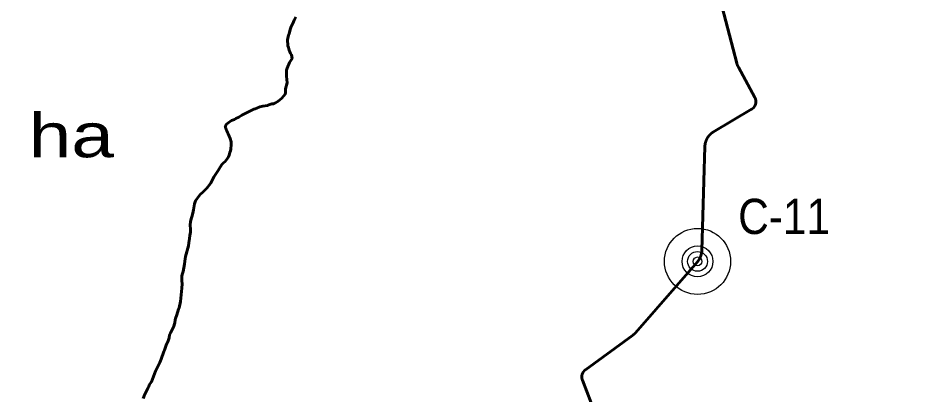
# Model space of a CAD drawing. Extents: x -1643653 to 4543381, y 1624270 to 13878484.
# Drawn here: x 645322 to 655603, y 8957191 to 8961468 of the extents above; entities that cross this region are included whole.
import ezdxf

# ---------------------------------------------------------------- set-up
doc = ezdxf.new("R2010")
doc.units = 0
doc.header["$LTSCALE"] = 200
for name, color, linetype, lineweight in [('1', 7, 'Continuous', 13), ('15', 7, 'Continuous', 25), ('24', 7, 'Continuous', 25), ('27', 7, 'Continuous', 53), ('60', 7, 'Continuous', 53)]:
    doc.layers.add(name, color=color, linetype=linetype, lineweight=lineweight)
doc.layers.add('63', color=7, linetype='Continuous')

msp = doc.modelspace()

# ---------------------------------------------------------------- linework, layer by layer
at = {"layer": '1', "lineweight": 25}
msp.add_spline([(814781, 9009175.5), (814787.2, 9009173.4), (814796.9, 9009173.4), (814799.4, 9009172.4), (814805.1, 9009174.5), (814805.6, 9009176.5), (814811.7, 9009179.5), (814811.7, 9009179.5), (814801.5, 9009181), (814790.7, 9009181.5), (814784.1, 9009183.1), (814777.4, 9009185.1), (814778.4, 9009175.5)], degree=3, dxfattribs=at)
at = {"layer": '15'}
for radius in [375, 175, 112.5, 50]:
    msp.add_circle((653034.2, 8958706.4), radius, dxfattribs=at)
at = {"layer": '24', "lineweight": 53}
for points in [[(648474.8, 8961478.5), (648456.4, 8961445.7), (648449.2, 8961427.1), (648419.2, 8961360.9), (648410.6, 8961337.9), (648398, 8961290.7), (648391.5, 8961272.8), (648380.9, 8961222.2), (648380.9, 8961222.2), (648379.8, 8961206.8), (648384.7, 8961171.6), (648385.1, 8961152.9)], [(648385.1, 8961152.9), (648390, 8961133.3), (648400.4, 8961103), (648415.7, 8961067.9), (648425.4, 8961050), (648432.1, 8961011), (648401.9, 8960963.6), (648376.2, 8960898.2), (648370.1, 8960878.6), (648367.8, 8960859.9), (648367.9, 8960810.1), (648376.5, 8960734.5), (648357.4, 8960665.8), (648358.8, 8960619.8), (648351.9, 8960604.5), (648338.8, 8960585.2), (648311.2, 8960556.4), (648291.8, 8960541.2), (648269.8, 8960521), (648236.7, 8960501.1), (648220, 8960496.4), (648202.2, 8960494.8), (648170.1, 8960481.9), (648153, 8960477.4), (648100.1, 8960468.4), (648066.6, 8960460), (648032.2, 8960447.3), (648014.3, 8960438.5), (647997.2, 8960433), (647928.7, 8960400.9), (647863.5, 8960365.3), (647826.2, 8960342.8), (647793.8, 8960329), (647778, 8960318.3), (647744.3, 8960305.3), (647701.1, 8960277.2), (647689.4, 8960265.4), (647679.9, 8960250.9), (647675, 8960238.2), (647674.2, 8960228.6), (647680.1, 8960220.4), (647683.5, 8960203.8), (647689.9, 8960186.8), (647698.1, 8960170.3), (647708.3, 8960153.8), (647730.9, 8960100.4), (647739.1, 8960063.9), (647740.2, 8960032), (647736.1, 8959980.6), (647731.8, 8959962.6), (647725, 8959943.9), (647716.7, 8959911.2), (647708.7, 8959892.6), (647696.4, 8959871.2), (647672.6, 8959842), (647653.3, 8959825.7), (647636.4, 8959806.1), (647604.7, 8959757.9), (647594, 8959736.3), (647570, 8959703.3), (647547.8, 8959670.1), (647506.1, 8959591.7), (647464.3, 8959538.3), (647419.4, 8959492.2), (647388.5, 8959466.3), (647353, 8959421.6), (647336.2, 8959394.4), (647325.8, 8959358.5), (647311.8, 8959293.5), (647311.1, 8959273.8), (647298.8, 8959224.9), (647287.2, 8959190.6), (647279.5, 8959155.6), (647275.4, 8959122.1), (647277.5, 8959069.1), (647277.3, 8959036.4), (647271.1, 8959002.1), (647267.7, 8958967.1), (647258.4, 8958917.2), (647255, 8958883), (647222.6, 8958760.6), (647213.1, 8958710), (647209.8, 8958675.8), (647197.2, 8958591.6), (647186.1, 8958559), (647181, 8958538.7), (647179, 8958522.3), (647180.3, 8958485.5), (647185.2, 8958453), (647182.2, 8958403.1), (647164.1, 8958249.7), (647150.1, 8958180.3), (647142.6, 8958162.4), (647125.2, 8958100), (647110, 8958058), (647106, 8958041.7), (647101.7, 8958008.2), (647087.2, 8957958.4), (647087.2, 8957958.4), (647058.3, 8957911.3), (647050.3, 8957890.4)], [(647050.3, 8957890.4), (647042.3, 8957873.9), (647037.4, 8957839), (647027, 8957805.4), (647004.7, 8957754), (646983.9, 8957699.7), (646975.5, 8957682.5), (646947.2, 8957596.2), (646930.5, 8957560.2), (646917.2, 8957527.6), (646883.4, 8957459.8), (646834.7, 8957341.3), (646821.9, 8957322.3), (646811.7, 8957303.4), (646805, 8957286.3), (646794.6, 8957269.1), (646788.3, 8957250.5), (646761.3, 8957200.6), (646741.4, 8957150.7)]]:
    msp.add_lwpolyline(points, dxfattribs=at)
at = {"layer": '27'}
for points in [[(653189, 8962072.5), (653480.5, 8960954.9), (653480.7, 8960954.4), (653481.7, 8960950.6), (653482.8, 8960946.7), (653484.1, 8960942.9), (653485.3, 8960939.1), (653486.7, 8960935.4), (653488.2, 8960931.6), (653489.7, 8960927.9), (653491.2, 8960924.2), (653492.9, 8960920.6), (653494.6, 8960917), (653496.4, 8960913.4), (653498.3, 8960909.9), (653684.6, 8960567.2), (653684.8, 8960566.8), (653686.1, 8960564.3), (653687.3, 8960561.7), (653688.5, 8960559.2), (653689.6, 8960556.5), (653690.6, 8960553.9), (653691.5, 8960551.2), (653692.4, 8960548.5), (653693.2, 8960545.8), (653693.9, 8960543.1), (653694.5, 8960540.3), (653695.1, 8960537.6), (653695.5, 8960534.8), (653695.9, 8960532), (653696.2, 8960529.2), (653696.5, 8960526.3), (653696.6, 8960523.5)], [(653189, 8962072.5), (653480.5, 8960954.9), (653480.7, 8960954.4), (653481.7, 8960950.6), (653482.8, 8960946.7), (653484.1, 8960942.9), (653485.3, 8960939.1), (653486.7, 8960935.4), (653488.2, 8960931.6), (653489.7, 8960927.9), (653491.2, 8960924.2), (653492.9, 8960920.6), (653494.6, 8960917), (653496.4, 8960913.4), (653498.3, 8960909.9), (653684.6, 8960567.2), (653684.8, 8960566.8), (653686.1, 8960564.3), (653687.3, 8960561.7), (653688.5, 8960559.2), (653689.6, 8960556.5), (653690.6, 8960553.9), (653691.5, 8960551.2), (653692.4, 8960548.5), (653693.2, 8960545.8), (653693.9, 8960543.1), (653694.5, 8960540.3), (653695.1, 8960537.6), (653695.5, 8960534.8), (653695.9, 8960532), (653696.2, 8960529.2), (653696.5, 8960526.3), (653696.6, 8960523.5)], [(648385.1, 8961152.9), (648384.7, 8961171.6), (648379.8, 8961206.8), (648380.9, 8961222.2), (648380.9, 8961222.2), (648391.5, 8961272.8), (648398, 8961290.7), (648410.6, 8961337.9), (648419.2, 8961360.9), (648449.2, 8961427.1), (648456.4, 8961445.7), (648474.8, 8961478.5)], [(648385.1, 8961152.9), (648384.7, 8961171.6), (648379.8, 8961206.8), (648380.9, 8961222.2), (648380.9, 8961222.2), (648391.5, 8961272.8), (648398, 8961290.7), (648410.6, 8961337.9), (648419.2, 8961360.9), (648449.2, 8961427.1), (648456.4, 8961445.7), (648474.8, 8961478.5)], [(647050.3, 8957890.4), (647058.3, 8957911.3), (647087.2, 8957958.4), (647087.2, 8957958.4), (647101.7, 8958008.2), (647106, 8958041.7), (647110, 8958058), (647125.2, 8958100), (647142.6, 8958162.4), (647150.1, 8958180.3), (647164.1, 8958249.7), (647182.2, 8958403.1), (647185.2, 8958453), (647180.3, 8958485.5), (647179, 8958522.3), (647181, 8958538.7), (647186.1, 8958559), (647197.2, 8958591.6), (647209.8, 8958675.8), (647213.1, 8958710), (647222.6, 8958760.6), (647255, 8958883), (647258.4, 8958917.2), (647267.7, 8958967.1), (647271.1, 8959002.1), (647277.3, 8959036.4), (647277.5, 8959069.1), (647275.4, 8959122.1), (647279.5, 8959155.6), (647287.2, 8959190.6), (647298.8, 8959224.9), (647311.1, 8959273.8), (647311.8, 8959293.5), (647325.8, 8959358.5), (647336.2, 8959394.4), (647353, 8959421.6), (647388.5, 8959466.3), (647419.4, 8959492.2), (647464.3, 8959538.3), (647506.1, 8959591.7), (647547.8, 8959670.1), (647570, 8959703.3), (647594, 8959736.3), (647604.7, 8959757.9), (647636.4, 8959806.1), (647653.3, 8959825.7), (647672.6, 8959842), (647696.4, 8959871.2), (647708.7, 8959892.6), (647716.7, 8959911.2), (647725, 8959943.9), (647731.8, 8959962.6), (647736.1, 8959980.6), (647740.2, 8960032), (647739.1, 8960063.9), (647730.9, 8960100.4), (647708.3, 8960153.8), (647698.1, 8960170.3), (647689.9, 8960186.8), (647683.5, 8960203.8), (647680.1, 8960220.4), (647674.2, 8960228.6), (647675, 8960238.2), (647679.9, 8960250.9), (647689.4, 8960265.4), (647701.1, 8960277.2), (647744.3, 8960305.3), (647778, 8960318.3), (647793.8, 8960329), (647826.2, 8960342.8), (647863.5, 8960365.3), (647928.7, 8960400.9), (647997.2, 8960433), (648014.3, 8960438.5), (648032.2, 8960447.3), (648066.6, 8960460), (648100.1, 8960468.4), (648153, 8960477.4), (648170.1, 8960481.9), (648202.2, 8960494.8), (648220, 8960496.4), (648236.7, 8960501.1), (648269.8, 8960521), (648291.8, 8960541.2), (648311.2, 8960556.4), (648338.8, 8960585.2), (648351.9, 8960604.5), (648358.8, 8960619.8), (648357.4, 8960665.8), (648376.5, 8960734.5), (648367.9, 8960810.1), (648367.8, 8960859.9), (648370.1, 8960878.6), (648376.2, 8960898.2), (648401.9, 8960963.6), (648432.1, 8961011), (648425.4, 8961050), (648415.7, 8961067.9), (648400.4, 8961103), (648390, 8961133.3), (648385.1, 8961152.9)], [(647050.3, 8957890.4), (647058.3, 8957911.3), (647087.2, 8957958.4), (647087.2, 8957958.4), (647101.7, 8958008.2), (647106, 8958041.7), (647110, 8958058), (647125.2, 8958100), (647142.6, 8958162.4), (647150.1, 8958180.3), (647164.1, 8958249.7), (647182.2, 8958403.1), (647185.2, 8958453), (647180.3, 8958485.5), (647179, 8958522.3), (647181, 8958538.7), (647186.1, 8958559), (647197.2, 8958591.6), (647209.8, 8958675.8), (647213.1, 8958710), (647222.6, 8958760.6), (647255, 8958883), (647258.4, 8958917.2), (647267.7, 8958967.1), (647271.1, 8959002.1), (647277.3, 8959036.4), (647277.5, 8959069.1), (647275.4, 8959122.1), (647279.5, 8959155.6), (647287.2, 8959190.6), (647298.8, 8959224.9), (647311.1, 8959273.8), (647311.8, 8959293.5), (647325.8, 8959358.5), (647336.2, 8959394.4), (647353, 8959421.6), (647388.5, 8959466.3), (647419.4, 8959492.2), (647464.3, 8959538.3), (647506.1, 8959591.7), (647547.8, 8959670.1), (647570, 8959703.3), (647594, 8959736.3), (647604.7, 8959757.9), (647636.4, 8959806.1), (647653.3, 8959825.7), (647672.6, 8959842), (647696.4, 8959871.2), (647708.7, 8959892.6), (647716.7, 8959911.2), (647725, 8959943.9), (647731.8, 8959962.6), (647736.1, 8959980.6), (647740.2, 8960032), (647739.1, 8960063.9), (647730.9, 8960100.4), (647708.3, 8960153.8), (647698.1, 8960170.3), (647689.9, 8960186.8), (647683.5, 8960203.8), (647680.1, 8960220.4), (647674.2, 8960228.6), (647675, 8960238.2), (647679.9, 8960250.9), (647689.4, 8960265.4), (647701.1, 8960277.2), (647744.3, 8960305.3), (647778, 8960318.3), (647793.8, 8960329), (647826.2, 8960342.8), (647863.5, 8960365.3), (647928.7, 8960400.9), (647997.2, 8960433), (648014.3, 8960438.5), (648032.2, 8960447.3), (648066.6, 8960460), (648100.1, 8960468.4), (648153, 8960477.4), (648170.1, 8960481.9), (648202.2, 8960494.8), (648220, 8960496.4), (648236.7, 8960501.1), (648269.8, 8960521), (648291.8, 8960541.2), (648311.2, 8960556.4), (648338.8, 8960585.2), (648351.9, 8960604.5), (648358.8, 8960619.8), (648357.4, 8960665.8), (648376.5, 8960734.5), (648367.9, 8960810.1), (648367.8, 8960859.9), (648370.1, 8960878.6), (648376.2, 8960898.2), (648401.9, 8960963.6), (648432.1, 8961011), (648425.4, 8961050), (648415.7, 8961067.9), (648400.4, 8961103), (648390, 8961133.3), (648385.1, 8961152.9)], [(653696.6, 8960523.5), (653696.7, 8960520.7), (653696.7, 8960517.8), (653696.6, 8960515), (653696.5, 8960512.2), (653696.2, 8960509.4), (653695.9, 8960506.6), (653695.5, 8960503.8), (653695, 8960501), (653694.4, 8960498.2), (653693.8, 8960495.5), (653693.1, 8960492.7), (653692.3, 8960490), (653691.4, 8960487.3), (653690.5, 8960484.7), (653689.4, 8960482), (653688.3, 8960479.4), (653687.2, 8960476.8), (653685.9, 8960474.3), (653684.6, 8960471.8), (653683.2, 8960469.3), (653681.8, 8960466.9), (653680.3, 8960464.5), (653678.7, 8960462.2), (653677, 8960459.9), (653675.3, 8960457.6), (653673.5, 8960455.4), (653671.7, 8960453.3), (653669.8, 8960451.2), (653667.8, 8960449.2), (653665.8, 8960447.2), (653663.7, 8960445.2), (653661.6, 8960443.4), (653659.4, 8960441.6), (653657.2, 8960439.8), (653654.9, 8960438.1), (653652.6, 8960436.5), (653650.2, 8960435), (653647.8, 8960433.5), (653215.1, 8960176.1), (653214.3, 8960175.7), (653210.9, 8960173.6), (653207.5, 8960171.4), (653204.2, 8960169.2), (653200.9, 8960166.9), (653197.7, 8960164.5), (653194.5, 8960162.1), (653191.4, 8960159.6), (653188.3, 8960157), (653185.3, 8960154.4), (653182.3, 8960151.8), (653179.4, 8960149), (653176.5, 8960146.2), (653173.7, 8960143.4), (653171, 8960140.5), (653168.3, 8960137.5), (653165.6, 8960134.5), (653163.1, 8960131.5), (653160.5, 8960128.3), (653158.1, 8960125.2), (653155.7, 8960122), (653153.4, 8960118.7), (653151.1, 8960115.4), (653148.9, 8960112.1), (653146.8, 8960108.7), (653144.8, 8960105.3), (653142.8, 8960101.8), (653140.8, 8960098.3), (653139, 8960094.7), (653137.2, 8960091.1), (653135.5, 8960087.5), (653133.9, 8960083.9), (653132.3, 8960080.2), (653130.9, 8960076.5), (653129.5, 8960072.7), (653128.1, 8960069), (653126.9, 8960065.2), (653125.7, 8960061.3), (653124.6, 8960057.5), (653123.6, 8960053.6), (653122.6, 8960049.7), (653121.7, 8960045.8), (653120.9, 8960041.9), (653120.2, 8960038), (653119.6, 8960034), (653119, 8960030.1), (653118.6, 8960026.1), (653118.2, 8960022.1), (653117.8, 8960018.1), (653117.6, 8960014.1), (653117.5, 8960010.1), (653082.6, 8958828.8), (653082.6, 8958827.2), (653082.4, 8958823.2), (653082.1, 8958819.2), (653081.8, 8958815.2), (653081.3, 8958811.2), (653080.8, 8958807.2), (653080.2, 8958803.3), (653079.6, 8958799.3), (653078.8, 8958795.4)], [(653696.6, 8960523.5), (653696.7, 8960520.7), (653696.7, 8960517.8), (653696.6, 8960515), (653696.5, 8960512.2), (653696.2, 8960509.4), (653695.9, 8960506.6), (653695.5, 8960503.8), (653695, 8960501), (653694.4, 8960498.2), (653693.8, 8960495.5), (653693.1, 8960492.7), (653692.3, 8960490), (653691.4, 8960487.3), (653690.5, 8960484.7), (653689.4, 8960482), (653688.3, 8960479.4), (653687.2, 8960476.8), (653685.9, 8960474.3), (653684.6, 8960471.8), (653683.2, 8960469.3), (653681.8, 8960466.9), (653680.3, 8960464.5), (653678.7, 8960462.2), (653677, 8960459.9), (653675.3, 8960457.6), (653673.5, 8960455.4), (653671.7, 8960453.3), (653669.8, 8960451.2), (653667.8, 8960449.2), (653665.8, 8960447.2), (653663.7, 8960445.2), (653661.6, 8960443.4), (653659.4, 8960441.6), (653657.2, 8960439.8), (653654.9, 8960438.1), (653652.6, 8960436.5), (653650.2, 8960435), (653647.8, 8960433.5), (653215.1, 8960176.1), (653214.3, 8960175.7), (653210.9, 8960173.6), (653207.5, 8960171.4), (653204.2, 8960169.2), (653200.9, 8960166.9), (653197.7, 8960164.5), (653194.5, 8960162.1), (653191.4, 8960159.6), (653188.3, 8960157), (653185.3, 8960154.4), (653182.3, 8960151.8), (653179.4, 8960149), (653176.5, 8960146.2), (653173.7, 8960143.4), (653171, 8960140.5), (653168.3, 8960137.5), (653165.6, 8960134.5), (653163.1, 8960131.5), (653160.5, 8960128.3), (653158.1, 8960125.2), (653155.7, 8960122), (653153.4, 8960118.7), (653151.1, 8960115.4), (653148.9, 8960112.1), (653146.8, 8960108.7), (653144.8, 8960105.3), (653142.8, 8960101.8), (653140.8, 8960098.3), (653139, 8960094.7), (653137.2, 8960091.1), (653135.5, 8960087.5), (653133.9, 8960083.9), (653132.3, 8960080.2), (653130.9, 8960076.5), (653129.5, 8960072.7), (653128.1, 8960069), (653126.9, 8960065.2), (653125.7, 8960061.3), (653124.6, 8960057.5), (653123.6, 8960053.6), (653122.6, 8960049.7), (653121.7, 8960045.8), (653120.9, 8960041.9), (653120.2, 8960038), (653119.6, 8960034), (653119, 8960030.1), (653118.6, 8960026.1), (653118.2, 8960022.1), (653117.8, 8960018.1), (653117.6, 8960014.1), (653117.5, 8960010.1), (653082.6, 8958828.8), (653082.6, 8958827.2), (653082.4, 8958823.2), (653082.1, 8958819.2), (653081.8, 8958815.2), (653081.3, 8958811.2), (653080.8, 8958807.2), (653080.2, 8958803.3), (653079.6, 8958799.3), (653078.8, 8958795.4)], [(653078.8, 8958795.4), (653078, 8958791.5), (653077.1, 8958787.6), (653076.1, 8958783.7), (653075.1, 8958779.9), (653073.9, 8958776), (653072.7, 8958772.2), (653071.4, 8958768.4), (653070.1, 8958764.7), (653068.6, 8958761), (653067.1, 8958757.2), (653065.5, 8958753.6), (653063.9, 8958749.9), (653062.2, 8958746.3), (653060.3, 8958742.8), (653058.5, 8958739.2), (653056.5, 8958735.7), (653054.5, 8958732.3), (653052.4, 8958728.9), (653050.3, 8958725.5), (653048.1, 8958722.2), (653045.8, 8958718.9), (653043.4, 8958715.6), (653041, 8958712.4), (653038.5, 8958709.3), (653036, 8958706.2), (653033.4, 8958703.2), (652328.7, 8957895.8), (652328.3, 8957895.4), (652325.7, 8957892.4), (652322.9, 8957889.5), (652320.1, 8957886.6), (652317.3, 8957883.8), (652314.4, 8957881.1), (652311.5, 8957878.3), (652308.4, 8957875.7), (652305.4, 8957873.1), (652302.3, 8957870.6), (652299.1, 8957868.2), (652295.9, 8957865.8), (651761.8, 8957476), (651761.3, 8957475.7), (651759, 8957474), (651756.8, 8957472.2), (651754.7, 8957470.3), (651752.6, 8957468.4), (651750.5, 8957466.5), (651748.5, 8957464.5), (651746.6, 8957462.4), (651744.7, 8957460.3), (651742.9, 8957458.1), (651741.2, 8957455.9), (651739.5, 8957453.6), (651737.9, 8957451.3), (651736.3, 8957448.9), (651734.8, 8957446.5), (651733.4, 8957444.1), (651732.1, 8957441.6), (651730.8, 8957439.1), (651729.6, 8957436.5), (651728.5, 8957433.9), (651727.4, 8957431.3), (651726.4, 8957428.6), (651725.5, 8957425.9), (651724.7, 8957423.2), (651724, 8957420.5), (651723.3, 8957417.8), (651722.7, 8957415), (651722.2, 8957412.2), (651721.7, 8957409.4), (651721.4, 8957406.6), (651721.1, 8957403.8), (651720.9, 8957401), (651720.8, 8957398.2), (651720.7, 8957395.3), (651720.8, 8957392.5), (651720.9, 8957389.7), (651721.1, 8957386.9), (651721.3, 8957384), (651721.7, 8957381.2), (651722.1, 8957378.4), (651722.7, 8957375.7), (651723.2, 8957372.9), (651723.9, 8957370.2), (651724.7, 8957367.4), (651725.5, 8957364.7), (651726.4, 8957362), (651727.4, 8957359.4), (652073.6, 8956458.6)], [(653078.8, 8958795.4), (653078, 8958791.5), (653077.1, 8958787.6), (653076.1, 8958783.7), (653075.1, 8958779.9), (653073.9, 8958776), (653072.7, 8958772.2), (653071.4, 8958768.4), (653070.1, 8958764.7), (653068.6, 8958761), (653067.1, 8958757.2), (653065.5, 8958753.6), (653063.9, 8958749.9), (653062.2, 8958746.3), (653060.3, 8958742.8), (653058.5, 8958739.2), (653056.5, 8958735.7), (653054.5, 8958732.3), (653052.4, 8958728.9), (653050.3, 8958725.5), (653048.1, 8958722.2), (653045.8, 8958718.9), (653043.4, 8958715.6), (653041, 8958712.4), (653038.5, 8958709.3), (653036, 8958706.2), (653033.4, 8958703.2), (652328.7, 8957895.8), (652328.3, 8957895.4), (652325.7, 8957892.4), (652322.9, 8957889.5), (652320.1, 8957886.6), (652317.3, 8957883.8), (652314.4, 8957881.1), (652311.5, 8957878.3), (652308.4, 8957875.7), (652305.4, 8957873.1), (652302.3, 8957870.6), (652299.1, 8957868.2), (652295.9, 8957865.8), (651761.8, 8957476), (651761.3, 8957475.7), (651759, 8957474), (651756.8, 8957472.2), (651754.7, 8957470.3), (651752.6, 8957468.4), (651750.5, 8957466.5), (651748.5, 8957464.5), (651746.6, 8957462.4), (651744.7, 8957460.3), (651742.9, 8957458.1), (651741.2, 8957455.9), (651739.5, 8957453.6), (651737.9, 8957451.3), (651736.3, 8957448.9), (651734.8, 8957446.5), (651733.4, 8957444.1), (651732.1, 8957441.6), (651730.8, 8957439.1), (651729.6, 8957436.5), (651728.5, 8957433.9), (651727.4, 8957431.3), (651726.4, 8957428.6), (651725.5, 8957425.9), (651724.7, 8957423.2), (651724, 8957420.5), (651723.3, 8957417.8), (651722.7, 8957415), (651722.2, 8957412.2), (651721.7, 8957409.4), (651721.4, 8957406.6), (651721.1, 8957403.8), (651720.9, 8957401), (651720.8, 8957398.2), (651720.7, 8957395.3), (651720.8, 8957392.5), (651720.9, 8957389.7), (651721.1, 8957386.9), (651721.3, 8957384), (651721.7, 8957381.2), (651722.1, 8957378.4), (651722.7, 8957375.7), (651723.2, 8957372.9), (651723.9, 8957370.2), (651724.7, 8957367.4), (651725.5, 8957364.7), (651726.4, 8957362), (651727.4, 8957359.4), (652073.6, 8956458.6)], [(646741.4, 8957150.7), (646761.3, 8957200.6), (646788.3, 8957250.5), (646794.6, 8957269.1), (646805, 8957286.3), (646811.7, 8957303.4), (646821.9, 8957322.3), (646834.7, 8957341.3), (646883.4, 8957459.8), (646917.2, 8957527.6), (646930.5, 8957560.2), (646947.2, 8957596.2), (646975.5, 8957682.5), (646983.9, 8957699.7), (647004.7, 8957754), (647027, 8957805.4), (647037.4, 8957839), (647042.3, 8957873.9), (647050.3, 8957890.4)], [(646741.4, 8957150.7), (646761.3, 8957200.6), (646788.3, 8957250.5), (646794.6, 8957269.1), (646805, 8957286.3), (646811.7, 8957303.4), (646821.9, 8957322.3), (646834.7, 8957341.3), (646883.4, 8957459.8), (646917.2, 8957527.6), (646930.5, 8957560.2), (646947.2, 8957596.2), (646975.5, 8957682.5), (646983.9, 8957699.7), (647004.7, 8957754), (647027, 8957805.4), (647037.4, 8957839), (647042.3, 8957873.9), (647050.3, 8957890.4)]]:
    msp.add_lwpolyline(points, dxfattribs=at)
at = {"layer": '60'}
for points in [[(653696.6, 8960523.5), (653696.5, 8960526.3), (653696.2, 8960529.2), (653695.9, 8960532), (653695.5, 8960534.8), (653695.1, 8960537.6), (653694.5, 8960540.3), (653693.9, 8960543.1), (653693.2, 8960545.8), (653692.4, 8960548.5), (653691.5, 8960551.2), (653690.6, 8960553.9), (653689.6, 8960556.5), (653688.5, 8960559.2), (653687.3, 8960561.7), (653686.1, 8960564.3), (653684.8, 8960566.8), (653684.6, 8960567.2), (653498.3, 8960909.9), (653496.4, 8960913.4), (653494.6, 8960917), (653492.9, 8960920.6), (653491.2, 8960924.2), (653489.7, 8960927.9), (653488.2, 8960931.6), (653486.7, 8960935.4), (653485.3, 8960939.1), (653484.1, 8960942.9), (653482.8, 8960946.7), (653481.7, 8960950.6), (653480.7, 8960954.4), (653480.5, 8960954.9), (653189, 8962072.5)], [(653078.8, 8958795.4), (653079.6, 8958799.3), (653080.2, 8958803.3), (653080.8, 8958807.2), (653081.3, 8958811.2), (653081.8, 8958815.2), (653082.1, 8958819.2), (653082.4, 8958823.2), (653082.6, 8958827.2), (653082.6, 8958828.8), (653117.5, 8960010.1), (653117.6, 8960014.1), (653117.8, 8960018.1), (653118.2, 8960022.1), (653118.6, 8960026.1), (653119, 8960030.1), (653119.6, 8960034), (653120.2, 8960038), (653120.9, 8960041.9), (653121.7, 8960045.8), (653122.6, 8960049.7), (653123.6, 8960053.6), (653124.6, 8960057.5), (653125.7, 8960061.3), (653126.9, 8960065.2), (653128.1, 8960069), (653129.5, 8960072.7), (653130.9, 8960076.5), (653132.3, 8960080.2), (653133.9, 8960083.9), (653135.5, 8960087.5), (653137.2, 8960091.1), (653139, 8960094.7), (653140.8, 8960098.3), (653142.8, 8960101.8), (653144.8, 8960105.3), (653146.8, 8960108.7), (653148.9, 8960112.1), (653151.1, 8960115.4), (653153.4, 8960118.7), (653155.7, 8960122), (653158.1, 8960125.2), (653160.5, 8960128.3), (653163.1, 8960131.5), (653165.6, 8960134.5), (653168.3, 8960137.5), (653171, 8960140.5), (653173.7, 8960143.4), (653176.5, 8960146.2), (653179.4, 8960149), (653182.3, 8960151.8), (653185.3, 8960154.4), (653188.3, 8960157), (653191.4, 8960159.6), (653194.5, 8960162.1), (653197.7, 8960164.5), (653200.9, 8960166.9), (653204.2, 8960169.2), (653207.5, 8960171.4), (653210.9, 8960173.6), (653214.3, 8960175.7), (653215.1, 8960176.1), (653647.8, 8960433.5), (653650.2, 8960435), (653652.6, 8960436.5), (653654.9, 8960438.1), (653657.2, 8960439.8), (653659.4, 8960441.6), (653661.6, 8960443.4), (653663.7, 8960445.2), (653665.8, 8960447.2), (653667.8, 8960449.2), (653669.8, 8960451.2), (653671.7, 8960453.3), (653673.5, 8960455.4), (653675.3, 8960457.6), (653677, 8960459.9), (653678.7, 8960462.2), (653680.3, 8960464.5), (653681.8, 8960466.9), (653683.2, 8960469.3), (653684.6, 8960471.8), (653685.9, 8960474.3), (653687.2, 8960476.8), (653688.3, 8960479.4), (653689.4, 8960482), (653690.5, 8960484.7), (653691.4, 8960487.3), (653692.3, 8960490), (653693.1, 8960492.7), (653693.8, 8960495.5), (653694.4, 8960498.2), (653695, 8960501), (653695.5, 8960503.8), (653695.9, 8960506.6), (653696.2, 8960509.4), (653696.5, 8960512.2), (653696.6, 8960515), (653696.7, 8960517.8), (653696.7, 8960520.7), (653696.6, 8960523.5)], [(652073.6, 8956458.6), (651727.4, 8957359.4), (651726.4, 8957362), (651725.5, 8957364.7), (651724.7, 8957367.4), (651723.9, 8957370.2), (651723.2, 8957372.9), (651722.7, 8957375.7), (651722.1, 8957378.4), (651721.7, 8957381.2), (651721.3, 8957384), (651721.1, 8957386.9), (651720.9, 8957389.7), (651720.8, 8957392.5), (651720.7, 8957395.3), (651720.8, 8957398.2), (651720.9, 8957401), (651721.1, 8957403.8), (651721.4, 8957406.6), (651721.7, 8957409.4), (651722.2, 8957412.2), (651722.7, 8957415), (651723.3, 8957417.8), (651724, 8957420.5), (651724.7, 8957423.2), (651725.5, 8957425.9), (651726.4, 8957428.6), (651727.4, 8957431.3), (651728.5, 8957433.9), (651729.6, 8957436.5), (651730.8, 8957439.1), (651732.1, 8957441.6), (651733.4, 8957444.1), (651734.8, 8957446.5), (651736.3, 8957448.9), (651737.9, 8957451.3), (651739.5, 8957453.6), (651741.2, 8957455.9), (651742.9, 8957458.1), (651744.7, 8957460.3), (651746.6, 8957462.4), (651748.5, 8957464.5), (651750.5, 8957466.5), (651752.6, 8957468.4), (651754.7, 8957470.3), (651756.8, 8957472.2), (651759, 8957474), (651761.3, 8957475.7), (651761.8, 8957476), (652295.9, 8957865.8), (652299.1, 8957868.2), (652302.3, 8957870.6), (652305.4, 8957873.1), (652308.4, 8957875.7), (652311.5, 8957878.3), (652314.4, 8957881.1), (652317.3, 8957883.8), (652320.1, 8957886.6), (652322.9, 8957889.5), (652325.7, 8957892.4), (652328.3, 8957895.4), (652328.7, 8957895.8), (653033.4, 8958703.2), (653036, 8958706.2), (653038.5, 8958709.3), (653041, 8958712.4), (653043.4, 8958715.6), (653045.8, 8958718.9), (653048.1, 8958722.2), (653050.3, 8958725.5), (653052.4, 8958728.9), (653054.5, 8958732.3), (653056.5, 8958735.7), (653058.5, 8958739.2), (653060.3, 8958742.8), (653062.2, 8958746.3), (653063.9, 8958749.9), (653065.5, 8958753.6), (653067.1, 8958757.2), (653068.6, 8958761), (653070.1, 8958764.7), (653071.4, 8958768.4), (653072.7, 8958772.2), (653073.9, 8958776), (653075.1, 8958779.9), (653076.1, 8958783.7), (653077.1, 8958787.6), (653078, 8958791.5), (653078.8, 8958795.4)]]:
    msp.add_lwpolyline(points, dxfattribs=at)

# ---------------------------------------------------------------- texts
at = {"layer": '15', "width": 0.9}
msp.add_text('C-11', height=400, dxfattribs=at).set_placement((653495.5, 8959017.2))
at = {"layer": '63', "width": 1.3}
msp.add_text(' 14080.90 ha', height=500, dxfattribs=at).set_placement((641333.9, 8959888.4))

doc.saveas('drawing.dxf')
